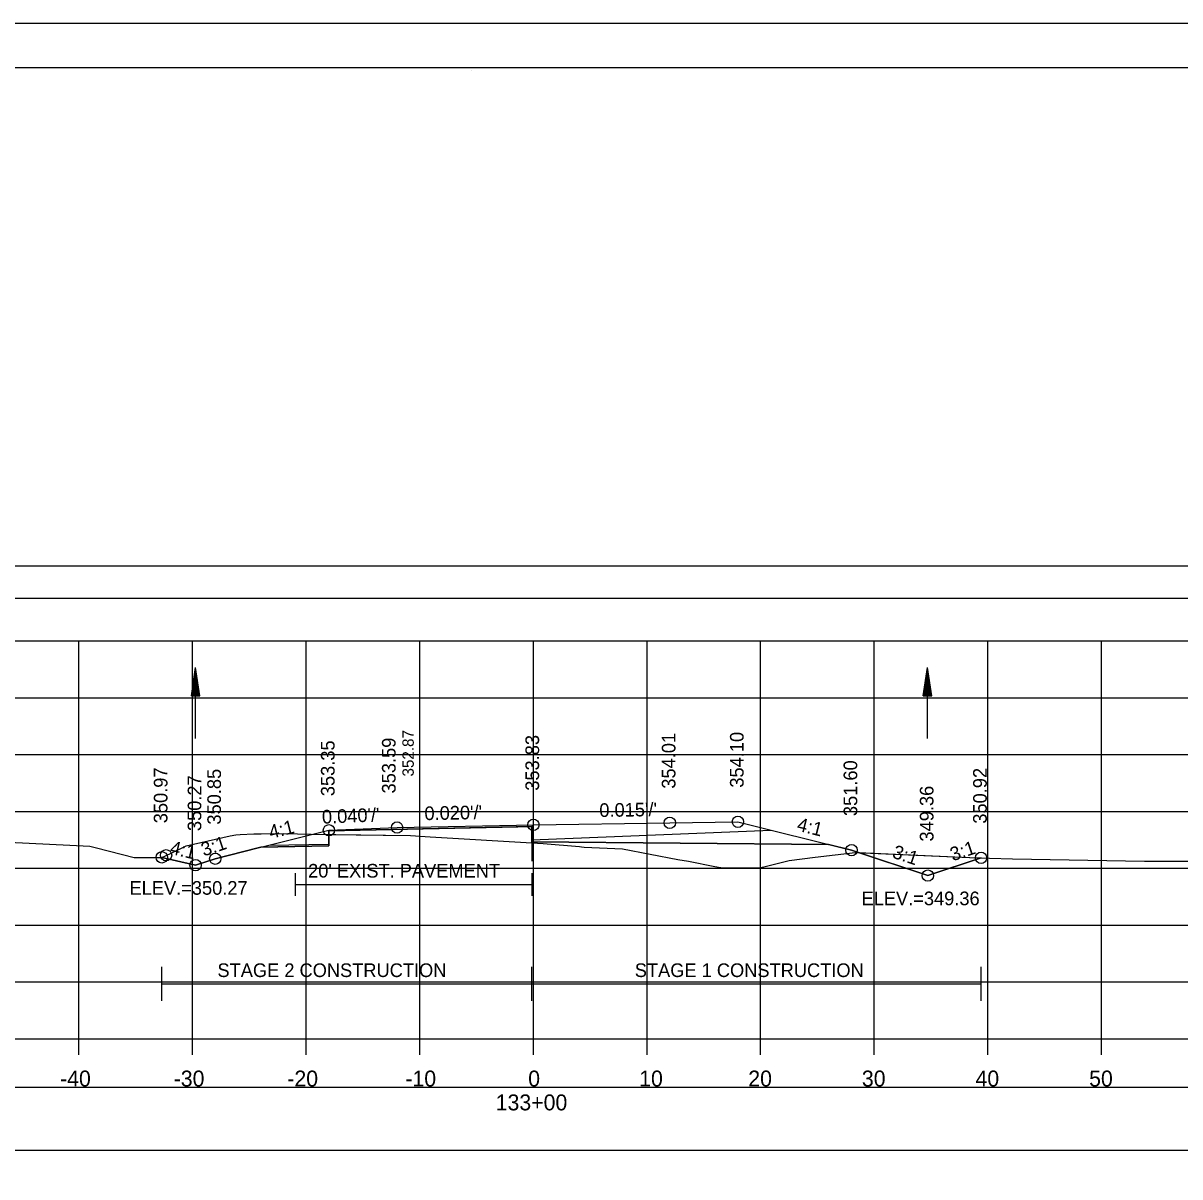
# Model space of a CAD drawing. Extents: x 1376273 to 1384221, y 378927 to 384592.
# Drawn here: x 1377012.9 to 1377114.7, y 381503.7 to 381605.2 of the extents above; entities that cross this region are included whole.
import ezdxf

# ---------------------------------------------------------------- set-up
doc = ezdxf.new("R2010")
doc.units = 0
for name, color, linetype in [('R_Alt Surface', 7, 'Continuous'), ('R_Axis', 7, 'Continuous'), ('R_Axis Annot', 7, 'Continuous'), ('R_Border', 7, 'Continuous'), ('R_Border Notes', 7, 'Continuous'), ('R_Dimension', 7, 'Continuous'), ('R_Exist Surface', 7, 'Continuous'), ('R_Fin Surface', 7, 'Continuous'), ('R_Grid', 7, 'Continuous'), ('R_No Plot', 7, 'Continuous'), ('R_Water', 7, 'Continuous'), ('R_Xsect Elev', 7, 'Continuous'), ('R_Xsect Slope', 7, 'Continuous'), ('T_Detection Zones', 7, 'Continuous'), ('T_Vehicle Path Lt Minor', 7, 'Continuous')]:
    doc.layers.add(name, color=color, linetype=linetype)

msp = doc.modelspace()

# ---------------------------------------------------------------- linework, layer by layer
at = {"layer": 'R_Alt Surface'}
for points in [[(1377034.49, 381532.88), (1377039.76, 381532.98), (1377039.77, 381534.15), (1377057.77, 381534.51), (1377057.62, 381534.51), (1377057.63, 381533.34), (1377078.69, 381534.21)], [(1377036.79, 381530.42), (1377036.79, 381528.42)], [(1377057.62, 381530.42), (1377057.62, 381528.42)], [(1377036.79, 381529.42), (1377057.62, 381529.42)]]:
    msp.add_lwpolyline(points, dxfattribs=at)
at = {"layer": 'R_Axis'}
for p, q in [((1376907.77, 381515.85), (1377207.77, 381515.85)), ((1377017.77, 381514.45), (1377017.77, 381515.85)), ((1377027.77, 381514.45), (1377027.77, 381515.85)), ((1377037.77, 381514.45), (1377037.77, 381515.85)), ((1377047.77, 381514.45), (1377047.77, 381515.85)), ((1377057.77, 381514.45), (1377057.77, 381515.85)), ((1377067.77, 381514.45), (1377067.77, 381515.85)), ((1377077.77, 381514.45), (1377077.77, 381515.85)), ((1377087.77, 381514.45), (1377087.77, 381515.85)), ((1377097.77, 381514.45), (1377097.77, 381515.85)), ((1377107.77, 381514.45), (1377107.77, 381515.85))]:
    msp.add_line(p, q, dxfattribs=at)
at = {"layer": 'R_Axis Annot'}
for points in [[(1376907.2, 381554.61), (1377209.01, 381554.61), (1377209.01, 381557.42), (1376907.2, 381557.42)], [(1376907.2, 381506.05), (1377209.01, 381506.05), (1377209.01, 381511.57), (1376907.2, 381511.57)]]:
    msp.add_lwpolyline(points, close=True, dxfattribs=at)
at = {"layer": 'R_Border'}
for p, q in [((1376899.77, 381601.31), (1377215.95, 381601.31)), ((1377052.29, 381601.05), (1377052.29, 381601.05)), ((1377052.29, 381601.05), (1377052.29, 381601.05))]:
    msp.add_line(p, q, dxfattribs=at)
at = {"layer": 'R_Dimension'}
for p, q in [((1377025.06, 381519.18), (1377025.06, 381522.18)), ((1377057.62, 381519.18), (1377057.62, 381522.18)), ((1377097.17, 381519.18), (1377097.17, 381522.18)), ((1377025.06, 381520.68), (1377097.17, 381520.68))]:
    msp.add_line(p, q, dxfattribs=at)
at = {"layer": 'R_Exist Surface'}
msp.add_lwpolyline([(1377011.59, 381533.14), (1377016.96, 381532.88), (1377018.72, 381532.79), (1377019.32, 381532.66), (1377022.62, 381531.81), (1377023.24, 381531.81), (1377025.06, 381531.81), (1377025.83, 381532.16), (1377027.21, 381532.82), (1377031.07, 381533.69), (1377031.57, 381533.79), (1377031.97, 381533.81), (1377033.17, 381533.88), (1377033.81, 381533.88), (1377035.79, 381533.9), (1377038.21, 381533.85), (1377046.94, 381533.72), (1377048.68, 381533.61), (1377058.62, 381533.03), (1377061.82, 381532.75), (1377061.99, 381532.73), (1377062.24, 381532.72), (1377065.62, 381532.55), (1377070.48, 381531.63), (1377071.42, 381531.48), (1377073.73, 381531.01), (1377074.24, 381530.91), (1377074.31, 381530.9), (1377077.59, 381530.89), (1377077.72, 381530.89), (1377077.92, 381530.94), (1377080.28, 381531.53), (1377082.56, 381531.83), (1377086.08, 381532.25), (1377096.83, 381531.78), (1377097.9, 381531.73), (1377099.92, 381531.69), (1377111.54, 381531.47), (1377113.58, 381531.46), (1377117.39, 381531.46)], dxfattribs=at)
at = {"layer": 'R_Fin Surface'}
msp.add_lwpolyline([(1377025.06, 381531.81), (1377028.04, 381531.12), (1377029.77, 381531.69), (1377033.53, 381532.64), (1377039.77, 381534.19), (1377045.77, 381534.43), (1377057.77, 381534.67), (1377069.77, 381534.85), (1377075.77, 381534.94), (1377085.77, 381532.44), (1377092.48, 381530.2), (1377097.17, 381531.77)], dxfattribs=at)
at = {"layer": 'R_Grid'}
for p, q in [((1376907.77, 381550.85), (1377207.77, 381550.85)), ((1376907.77, 381550.85), (1377207.77, 381550.85)), ((1377017.77, 381515.85), (1377017.77, 381550.85)), ((1377017.77, 381515.85), (1377017.77, 381550.85)), ((1377027.77, 381515.85), (1377027.77, 381550.85)), ((1377027.77, 381515.85), (1377027.77, 381550.85)), ((1377037.77, 381515.85), (1377037.77, 381550.85)), ((1377037.77, 381515.85), (1377037.77, 381550.85)), ((1377047.77, 381515.85), (1377047.77, 381550.85)), ((1377047.77, 381515.85), (1377047.77, 381550.85)), ((1377057.77, 381515.85), (1377057.77, 381550.85)), ((1377057.77, 381515.85), (1377057.77, 381550.85)), ((1377067.77, 381515.85), (1377067.77, 381550.85)), ((1377067.77, 381515.85), (1377067.77, 381550.85)), ((1377077.77, 381515.85), (1377077.77, 381550.85)), ((1377077.77, 381515.85), (1377077.77, 381550.85)), ((1377087.77, 381515.85), (1377087.77, 381550.85)), ((1377087.77, 381515.85), (1377087.77, 381550.85)), ((1377097.77, 381515.85), (1377097.77, 381550.85)), ((1377097.77, 381515.85), (1377097.77, 381550.85)), ((1377107.77, 381515.85), (1377107.77, 381550.85)), ((1377107.77, 381515.85), (1377107.77, 381550.85)), ((1376907.77, 381545.85), (1377207.77, 381545.85)), ((1376907.77, 381545.85), (1377207.77, 381545.85)), ((1376907.77, 381540.85), (1377207.77, 381540.85)), ((1376907.77, 381540.85), (1377207.77, 381540.85)), ((1376907.77, 381535.85), (1377207.77, 381535.85)), ((1376907.77, 381535.85), (1377207.77, 381535.85)), ((1376907.77, 381530.85), (1377207.77, 381530.85)), ((1376907.77, 381530.85), (1377207.77, 381530.85)), ((1376907.77, 381525.85), (1377207.77, 381525.85)), ((1376907.77, 381525.85), (1377207.77, 381525.85)), ((1376907.77, 381520.85), (1377207.77, 381520.85)), ((1376907.77, 381520.85), (1377207.77, 381520.85)), ((1376907.77, 381515.85), (1377207.77, 381515.85)), ((1376907.77, 381515.85), (1377207.77, 381515.85))]:
    msp.add_line(p, q, dxfattribs=at)
at = {"layer": 'R_No Plot'}
msp.add_line((1376887.37, 381605.2), (1377220.7, 381605.2), dxfattribs=at)
for points in [[(1376887.36, 381605.2), (1377220.7, 381605.2), (1377220.7, 381391.86), (1376887.36, 381391.86)], [(1377133.69, 381601.31), (1377133.69, 381591.43), (1377169.42, 381591.43), (1377169.42, 381588.51), (1377192.62, 381588.51), (1377192.62, 381564.17), (1377215.95, 381564.17), (1377215.95, 381395.85), (1376899.77, 381395.85), (1376899.77, 381601.31)]]:
    msp.add_lwpolyline(points, close=True, dxfattribs=at)
msp.add_lwpolyline([(1377033.78, 381532.7), (1377039.76, 381532.82), (1377039.77, 381534.15), (1377057.77, 381534.51), (1377057.62, 381534.51), (1377057.63, 381533.18), (1377083.74, 381532.95)], dxfattribs=at)
for centre in [(1377057.77, 381534.67), (1377057.77, 381534.67), (1377069.77, 381534.85), (1377069.77, 381534.85), (1377075.77, 381534.94), (1377075.77, 381534.94), (1377039.77, 381534.19), (1377039.77, 381534.19), (1377045.77, 381534.43), (1377045.77, 381534.43), (1377025.06, 381531.81), (1377025.44, 381531.99), (1377029.77, 381531.69), (1377029.77, 381531.69), (1377085.77, 381532.44), (1377085.77, 381532.44), (1377097.17, 381531.77), (1377097.17, 381531.77), (1377028.04, 381531.12), (1377028.04, 381531.12), (1377028.04, 381531.12), (1377028.04, 381531.12), (1377092.48, 381530.2), (1377092.48, 381530.2), (1377092.48, 381530.2), (1377092.48, 381530.2)]:
    msp.add_circle(centre, 0.5, dxfattribs=at)
at = {"layer": 'R_Water'}
for p, q in [((1377027.67, 381546.02), (1377028.04, 381548.52)), ((1377028.04, 381542.27), (1377028.04, 381548.52)), ((1377028.42, 381546.02), (1377028.04, 381548.52)), ((1377092.08, 381546.02), (1377092.45, 381548.52)), ((1377092.45, 381542.27), (1377092.45, 381548.52)), ((1377092.83, 381546.02), (1377092.45, 381548.52)), ((1377027.73, 381546.02), (1377028.04, 381548.1)), ((1377027.79, 381546.02), (1377028.04, 381547.67)), ((1377028.35, 381546.02), (1377028.04, 381548.1)), ((1377028.29, 381546.02), (1377028.04, 381547.67)), ((1377092.14, 381546.02), (1377092.45, 381548.1)), ((1377092.2, 381546.02), (1377092.45, 381547.67)), ((1377092.77, 381546.02), (1377092.45, 381548.1)), ((1377092.7, 381546.02), (1377092.45, 381547.67)), ((1377027.85, 381546.02), (1377028.04, 381547.25)), ((1377027.92, 381546.02), (1377028.04, 381546.83)), ((1377027.98, 381546.02), (1377028.04, 381546.41)), ((1377028.23, 381546.02), (1377028.04, 381547.25)), ((1377028.16, 381546.02), (1377028.04, 381546.83)), ((1377028.1, 381546.02), (1377028.04, 381546.41)), ((1377092.27, 381546.02), (1377092.45, 381547.25)), ((1377092.33, 381546.02), (1377092.45, 381546.83)), ((1377092.39, 381546.02), (1377092.45, 381546.41)), ((1377092.64, 381546.02), (1377092.45, 381547.25)), ((1377092.58, 381546.02), (1377092.45, 381546.83)), ((1377092.51, 381546.02), (1377092.45, 381546.41)), ((1377027.67, 381546.02), (1377028.42, 381546.02)), ((1377092.08, 381546.02), (1377092.83, 381546.02))]:
    msp.add_line(p, q, dxfattribs=at)
at = {"layer": 'T_Detection Zones'}
for p, q in [((1377057.63, 381533.18), (1377057.63, 381531.47)), ((1377083.74, 381532.95), (1377057.63, 381533.18)), ((1377057.63, 381533.18), (1377057.63, 381533.09)), ((1377085.77, 381532.44), (1377083.74, 381532.95)), ((1377086.39, 381532.23), (1377085.77, 381532.44))]:
    msp.add_line(p, q, dxfattribs=at)
for points in [[(1377025.06, 381531.81), (1377025.83, 381532.16), (1377027.21, 381532.82), (1377031.07, 381533.69), (1377031.57, 381533.79), (1377031.97, 381533.81), (1377033.17, 381533.88), (1377033.81, 381533.88), (1377035.79, 381533.9), (1377038.21, 381533.85), (1377039.76, 381533.83), (1377039.76, 381532.82), (1377033.78, 381532.7), (1377033.53, 381532.64), (1377029.77, 381531.69), (1377028.04, 381531.12)], [(1377086.39, 381532.23), (1377096.83, 381531.78), (1377097.17, 381531.77), (1377092.48, 381530.2)]]:
    msp.add_lwpolyline(points, close=True, dxfattribs=at)
msp.add_lwpolyline([(1377057.63, 381533.09), (1377058.62, 381533.03), (1377061.82, 381532.75), (1377061.99, 381532.73), (1377062.24, 381532.72), (1377065.62, 381532.55), (1377070.48, 381531.63), (1377071.42, 381531.48), (1377073.73, 381531.01), (1377074.24, 381530.91), (1377074.31, 381530.9), (1377077.59, 381530.89), (1377077.72, 381530.89), (1377077.92, 381530.94), (1377080.28, 381531.53), (1377082.56, 381531.83), (1377086.08, 381532.25), (1377086.39, 381532.23)], dxfattribs=at)
at = {"layer": 'T_Vehicle Path Lt Minor'}
msp.add_line((1377057.63, 381533.09), (1377057.63, 381533.18), dxfattribs=at)
for points in [[(1377057.63, 381533.18), (1377057.62, 381534.51), (1377039.77, 381534.15), (1377039.76, 381533.83)], [(1377039.76, 381533.83), (1377046.94, 381533.72), (1377048.68, 381533.61), (1377057.63, 381533.09)]]:
    msp.add_lwpolyline(points, dxfattribs=at)

# ---------------------------------------------------------------- texts
at = {"layer": 'R_Alt Surface'}
msp.add_text("20' EXIST. PAVEMENT", height=1.2, dxfattribs=at).set_placement((1377037.94, 381530.03))
at = {"layer": 'R_Axis Annot'}
for s, p in [('-40', (1377016.11, 381511.65)), ('-30', (1377026.11, 381511.65)), ('-20', (1377036.11, 381511.65)), ('-10', (1377046.5, 381511.65)), ('0', (1377057.31, 381511.65)), ('10', (1377067.08, 381511.65)), ('20', (1377076.68, 381511.65)), ('30', (1377086.68, 381511.65)), ('40', (1377096.68, 381511.65)), ('50', (1377106.68, 381511.65)), ('133+00', (1377054.45, 381509.55))]:
    msp.add_text(s, height=1.4, dxfattribs=at).set_placement(p)
at = {"layer": 'R_Border Notes'}
for s, p in [('ELEV.=350.27', (1377022.22, 381528.52)), ('ELEV.=349.36', (1377086.65, 381527.6))]:
    msp.add_text(s, height=1.2, dxfattribs=at).set_placement(p)
at = {"layer": 'R_Dimension'}
for s, p in [('STAGE 2 CONSTRUCTION', (1377029.96, 381521.28)), ('STAGE 1 CONSTRUCTION', (1377066.69, 381521.28))]:
    msp.add_text(s, height=1.2, dxfattribs=at).set_placement(p)
at = {"layer": 'R_Xsect Elev'}
for s, height, p in [('353.59', 1.2, (1377045.64, 381537.43)), ('352.87', 1, (1377047.24, 381538.92)), ('353.83', 1.2, (1377058.27, 381537.67)), ('354.01', 1.2, (1377070.27, 381537.85)), ('354.10', 1.2, (1377076.27, 381537.94)), ('353.35', 1.2, (1377040.27, 381537.19)), ('351.60', 1.2, (1377086.27, 381535.44)), ('350.97', 1.2, (1377025.56, 381534.81)), ('350.85', 1.2, (1377030.27, 381534.69)), ('350.92', 1.2, (1377097.67, 381534.77)), ('350.27', 1.2, (1377028.54, 381534.12)), ('349.36', 1.2, (1377092.98, 381533.2))]:
    msp.add_text(s, height=height, rotation=90, dxfattribs=at).set_placement(p)
at = {"layer": 'R_Xsect Slope'}
for s, rotation, p in [("0.040'/'", 2.2906, (1377039.18, 381534.77)), ("0.020'/'", 1.1458, (1377048.19, 381535.08)), ("0.015'/'", 0.8499, (1377063.58, 381535.36)), ('4:1', 345.9638, (1377080.89, 381534.18)), ('4:1', 14.0362, (1377034.65, 381533.43)), ('4:1', 346.8912, (1377025.72, 381532.13)), ('3:1', 18.4349, (1377028.75, 381531.88)), ('3:1', 18.4349, (1377094.67, 381531.46)), ('3:1', 341.5651, (1377089.28, 381531.8))]:
    msp.add_text(s, height=1.2, rotation=rotation, dxfattribs=at).set_placement(p)

doc.saveas('drawing.dxf')
